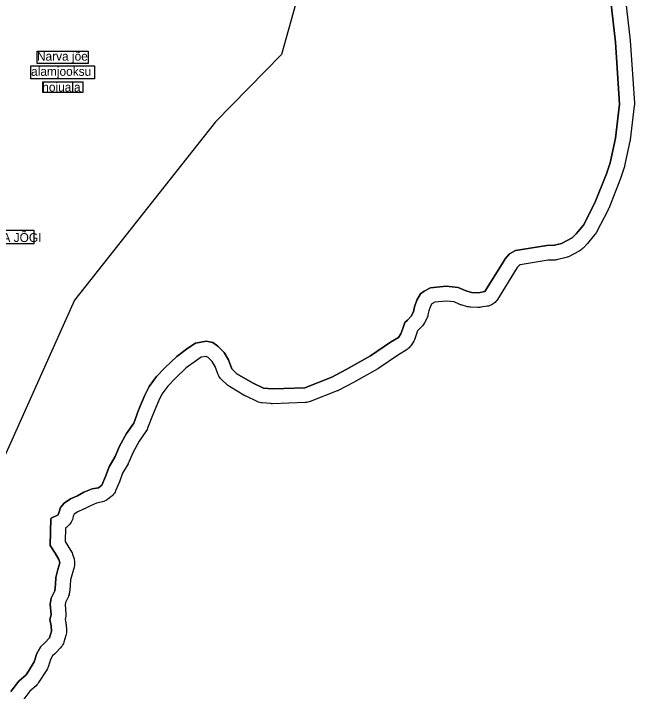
# Model space of a CAD drawing. Extents: x 728832 to 739469, y 6586263 to 6599699.
# Drawn here: x 738858.8 to 739277.9, y 6589449.5 to 6589907.2 of the extents above; entities that cross this region are included whole.
import ezdxf

# ---------------------------------------------------------------- set-up
doc = ezdxf.new("R2010")
doc.units = 0
for name, color, linetype in [('a_kalda_veekaitsev', 7, 'Continuous'), ('a_looduskaitse_voond', 7, 'Continuous'), ('a_veekogu_piir', 7, 'Continuous'), ('dp_hoonestus', 7, 'Continuous'), ('v_dp_situatsioon_tekst', 7, 'Continuous'), ('v_dp_tekst', 7, 'Continuous')]:
    doc.layers.add(name, color=color, linetype=linetype)

msp = doc.modelspace()

# ---------------------------------------------------------------- linework, layer by layer
at = {"layer": 'a_kalda_veekaitsev'}
for points in [[(738856.95, 6589449.31), (738862.4, 6589456.36), (738867.29, 6589460.76), (738868.82, 6589463.2), (738872.73, 6589469.37), (738874.42, 6589474.97), (738877.19, 6589479.75), (738880.02, 6589482.33), (738883.16, 6589485.7), (738884.51, 6589490.09), (738884.24, 6589493.84), (738883.41, 6589498.14), (738884.11, 6589501.28), (738883.63, 6589508.41), (738884.28, 6589512.41), (738886.62, 6589517.38), (738887.04, 6589521.58), (738887.26, 6589526.44), (738888.78, 6589531.84), (738890.04, 6589536.2), (738889.34, 6589538.52), (738886.8, 6589542.87), (738883.57, 6589548.02), (738883.83, 6589557.29), (738884.08, 6589565.9), (738884.09, 6589566.4), (738889.02, 6589568.73), (738889.49, 6589570.65), (738890.56, 6589573.74), (738893.03, 6589576.63), (738897.29, 6589579.6), (738902.04, 6589581.64), (738906.35, 6589583.91), (738911.89, 6589586.27), (738916.24, 6589587.04), (738918.45, 6589588.72), (738920.91, 6589594.6), (738923.38, 6589601.11), (738927.41, 6589608.16), (738930.38, 6589615.06), (738935.13, 6589623.68), (738939.96, 6589630.68), (738943.23, 6589639.37), (738947.44, 6589649.54), (738950.34, 6589655.38), (738955.29, 6589662.03), (738961, 6589668.04), (738968.98, 6589675.65), (738976.54, 6589681.24), (738981.67, 6589684.57), (738988.87, 6589685.87), (738993.27, 6589685.02), (738996.76, 6589682.58), (739000.87, 6589678.31), (739003.91, 6589673.29), (739006.09, 6589667.31), (739009.62, 6589663.94), (739020.03, 6589657.78), (739027.55, 6589654.24), (739033.37, 6589653.76), (739041.32, 6589653.93), (739055.36, 6589654.5), (739073.67, 6589661.7), (739083.31, 6589666.81), (739099.7, 6589676.05), (739113.25, 6589685.25), (739118.65, 6589688.53), (739120.26, 6589690.87), (739121.53, 6589694.46), (739122.89, 6589698.54), (739124.73, 6589700.26), (739127.25, 6589702.82), (739128.78, 6589705.84), (739129.5, 6589709.21), (739131.11, 6589713.71), (739133.47, 6589717.91), (739135.93, 6589719.79), (739140.29, 6589722.07), (739150.87, 6589723.14), (739158.82, 6589722.2), (739163.6, 6589720.09), (739167.9, 6589718.88), (739172.56, 6589718.72), (739176.97, 6589719.42), (739188.61, 6589738.24), (739190.63, 6589741.48), (739193.61, 6589745.05), (739197.67, 6589747.15), (739218.68, 6589750.55), (739223.89, 6589750.75), (739228.69, 6589751.88), (739235.93, 6589755.68), (739238.54, 6589758.47), (739243.44, 6589764.2), (739251.22, 6589779.29), (739258.94, 6589798.95), (739261.51, 6589806.46), (739265.09, 6589823.09), (739267.9, 6589846.01), (739265.09, 6589887.82), (739260.98, 6589923.4)], [(739270.92, 6589924.55), (739275.02, 6589888.97), (739277.88, 6589846.68), (739277.9, 6589846.05), (739277.88, 6589845.42), (739277.83, 6589844.79), (739275.02, 6589821.87), (739274.97, 6589821.57), (739274.92, 6589821.28), (739274.87, 6589820.98), (739271.28, 6589804.35), (739271.19, 6589803.98), (739271.09, 6589803.6), (739270.97, 6589803.23), (739268.41, 6589795.72), (739260.53, 6589775.64), (739260.4, 6589775.32), (739260.26, 6589775.01), (739260.11, 6589774.71), (739252.33, 6589759.62), (739251.95, 6589758.95), (739251.52, 6589758.31), (739251.04, 6589757.7), (739246.13, 6589751.97), (739243.24, 6589748.85), (739242.64, 6589748.26), (739241.99, 6589747.73), (739241.3, 6589747.24), (739240.58, 6589746.82), (739233.33, 6589743.02), (739232.57, 6589742.66), (739231.79, 6589742.37), (739230.98, 6589742.14), (739226.18, 6589741.01), (739225.54, 6589740.89), (739224.9, 6589740.8), (739224.26, 6589740.75), (739219.67, 6589740.58), (739200.84, 6589737.54), (739200, 6589737.1), (739198.76, 6589735.62), (739185.47, 6589714.15), (739184.99, 6589713.44), (739184.45, 6589712.78), (739183.85, 6589712.16), (739183.2, 6589711.59), (739182.5, 6589711.09), (739181.77, 6589710.64), (739181, 6589710.26), (739180.2, 6589709.95), (739179.37, 6589709.71), (739178.53, 6589709.54), (739174.12, 6589708.84), (739173.49, 6589708.77), (739172.86, 6589708.73), (739172.23, 6589708.73), (739167.57, 6589708.88), (739166.77, 6589708.94), (739165.97, 6589709.06), (739165.19, 6589709.25), (739160.89, 6589710.46), (739160.44, 6589710.6), (739159.99, 6589710.76), (739159.55, 6589710.94), (739156.15, 6589712.44), (739150.78, 6589713.08), (739143.22, 6589712.32), (739141.17, 6589711.21), (739140.24, 6589709.56), (739139.14, 6589706.47), (739138.55, 6589703.74), (739138.34, 6589702.92), (739138.06, 6589702.11), (739137.71, 6589701.34), (739136.18, 6589698.32), (739135.78, 6589697.6), (739135.33, 6589696.92), (739134.82, 6589696.28), (739134.26, 6589695.68), (739131.58, 6589693.06), (739129.71, 6589687.62), (739129.38, 6589686.78), (739128.98, 6589685.97), (739128.5, 6589685.2), (739126.89, 6589682.86), (739126.38, 6589682.19), (739125.82, 6589681.56), (739125.21, 6589680.98), (739124.55, 6589680.45), (739123.84, 6589679.98), (739118.66, 6589676.83), (739105.31, 6589667.78), (739105.08, 6589667.62), (739104.85, 6589667.48), (739104.61, 6589667.34), (739088.22, 6589658.1), (739078.35, 6589652.86), (739078.02, 6589652.69), (739077.68, 6589652.54), (739077.33, 6589652.39), (739059.02, 6589645.19), (739058.22, 6589644.91), (739057.39, 6589644.7), (739056.55, 6589644.57), (739055.7, 6589644.5), (739033.7, 6589643.76), (739033.32, 6589643.76), (739032.93, 6589643.77), (739032.54, 6589643.79), (739026.73, 6589644.27), (739025.84, 6589644.38), (739024.97, 6589644.58), (739024.12, 6589644.85), (739023.29, 6589645.19), (739015.77, 6589648.74), (739015.49, 6589648.87), (739015.21, 6589649.02), (739014.94, 6589649.17), (739004.53, 6589655.33), (739003.89, 6589655.75), (739003.28, 6589656.21), (739002.71, 6589656.71), (738999.18, 6589660.08), (738998.55, 6589660.74), (738997.98, 6589661.46), (738997.48, 6589662.23), (738997.05, 6589663.04), (738996.69, 6589663.88), (738994.85, 6589668.94), (738992.89, 6589672.18), (738990.23, 6589674.94), (738988.81, 6589675.7), (738985.42, 6589675.09), (738982.24, 6589673.02), (738975.43, 6589667.98), (738968.08, 6589660.98), (738962.95, 6589655.58), (738958.89, 6589650.12), (738956.54, 6589645.4), (738952.53, 6589635.7), (738949.32, 6589627.16), (738949, 6589626.41), (738948.62, 6589625.69), (738948.19, 6589625), (738943.65, 6589618.41), (738939.37, 6589610.66), (738936.59, 6589604.21), (738936.44, 6589603.87), (738936.27, 6589603.53), (738936.09, 6589603.2), (738932.45, 6589596.84), (738930.27, 6589591.06), (738927.67, 6589584.85), (738927.3, 6589584.06), (738926.86, 6589583.31), (738926.36, 6589582.6), (738925.79, 6589581.94), (738925.18, 6589581.33), (738924.51, 6589580.77), (738922.31, 6589579.09), (738921.52, 6589578.55), (738920.69, 6589578.09), (738919.82, 6589577.7), (738918.92, 6589577.41), (738917.99, 6589577.2), (738914.76, 6589576.62), (738910.64, 6589574.87), (738906.69, 6589572.79), (738906.46, 6589572.67), (738906.22, 6589572.56), (738905.98, 6589572.45), (738902.17, 6589570.82), (738899.8, 6589569.16), (738899.39, 6589568.67), (738899.09, 6589567.83), (738898.74, 6589566.38), (738898.49, 6589565.5), (738898.15, 6589564.65), (738897.74, 6589563.83), (738897.26, 6589563.06), (738896.71, 6589562.33), (738896.09, 6589561.66), (738895.42, 6589561.04), (738894.69, 6589560.49), (738893.91, 6589560.01), (738893.65, 6589550.69), (738897.89, 6589543.71), (738898.3, 6589542.97), (738898.64, 6589542.19), (738898.92, 6589541.39), (738899.62, 6589539.06), (738899.82, 6589538.28), (738899.95, 6589537.48), (738900.03, 6589536.67), (738900.03, 6589535.86), (738899.97, 6589535.05), (738899.84, 6589534.24), (738899.65, 6589533.45), (738897.19, 6589524.83), (738897.03, 6589521.14), (738897.02, 6589520.95), (738897.01, 6589520.76), (738896.99, 6589520.57), (738896.57, 6589516.37), (738896.44, 6589515.53), (738896.25, 6589514.71), (738895.99, 6589513.9), (738895.66, 6589513.12), (738893.93, 6589509.43), (738893.68, 6589507.94), (738894.08, 6589501.94), (738894.1, 6589500.99), (738894.03, 6589500.04), (738893.87, 6589499.1), (738893.62, 6589498), (738894.06, 6589495.75), (738894.13, 6589495.35), (738894.18, 6589494.95), (738894.22, 6589494.55), (738894.48, 6589490.8), (738894.51, 6589489.88), (738894.44, 6589488.96), (738894.3, 6589488.05), (738894.07, 6589487.16), (738892.72, 6589482.77), (738892.42, 6589481.91), (738892.04, 6589481.09), (738891.58, 6589480.31), (738891.06, 6589479.57), (738890.48, 6589478.88), (738887.34, 6589475.52), (738887.15, 6589475.32), (738886.95, 6589475.12), (738886.75, 6589474.94), (738885.07, 6589473.4), (738883.66, 6589470.96), (738882.3, 6589466.47), (738882, 6589465.63), (738881.63, 6589464.82), (738881.18, 6589464.04), (738875.75, 6589455.43), (738875.23, 6589454.67), (738874.63, 6589453.97), (738873.98, 6589453.33), (738869.76, 6589449.53), (738865.72, 6589444.3)]]:
    msp.add_lwpolyline(points, dxfattribs=at)
at = {"layer": 'a_looduskaitse_voond'}
for points in [[(738874.68, 6589881.78), (738909.22, 6589881.78), (738909.22, 6589873.48), (738874.68, 6589873.48)], [(738870.45, 6589871.79), (738913.35, 6589871.79), (738913.35, 6589863.18), (738870.45, 6589863.18)], [(738878.53, 6589861.13), (738905.68, 6589861.13), (738905.68, 6589853.91), (738878.53, 6589853.91)], [(738829.24, 6589761.03), (738872.61, 6589761.03), (738872.61, 6589751.77), (738829.24, 6589751.77)]]:
    msp.add_lwpolyline(points, close=True, dxfattribs=at)
at = {"layer": 'a_veekogu_piir'}
msp.add_lwpolyline([(739260.98, 6589923.4), (739265.09, 6589887.82), (739267.9, 6589846.01), (739265.09, 6589823.09), (739261.51, 6589806.46), (739258.94, 6589798.95), (739251.22, 6589779.29), (739243.44, 6589764.2), (739238.54, 6589758.47), (739235.93, 6589755.68), (739228.69, 6589751.88), (739223.89, 6589750.75), (739218.68, 6589750.55), (739197.67, 6589747.15), (739193.61, 6589745.05), (739190.63, 6589741.48), (739188.61, 6589738.24), (739176.97, 6589719.42), (739172.56, 6589718.72), (739167.9, 6589718.88), (739163.6, 6589720.09), (739158.82, 6589722.2), (739150.87, 6589723.14), (739140.29, 6589722.07), (739135.93, 6589719.79), (739133.47, 6589717.91), (739131.11, 6589713.71), (739129.5, 6589709.21), (739128.78, 6589705.84), (739127.25, 6589702.82), (739124.73, 6589700.26), (739122.89, 6589698.54), (739121.53, 6589694.46), (739120.26, 6589690.87), (739118.65, 6589688.53), (739113.25, 6589685.25), (739099.7, 6589676.05), (739083.31, 6589666.81), (739073.67, 6589661.7), (739055.36, 6589654.5), (739041.32, 6589653.93), (739033.37, 6589653.76), (739027.55, 6589654.24), (739020.03, 6589657.78), (739009.62, 6589663.94), (739006.09, 6589667.31), (739003.91, 6589673.29), (739000.87, 6589678.31), (738996.76, 6589682.58), (738993.27, 6589685.02), (738988.87, 6589685.87), (738981.67, 6589684.57), (738976.54, 6589681.24), (738968.98, 6589675.65), (738961, 6589668.04), (738955.29, 6589662.03), (738950.34, 6589655.38), (738947.44, 6589649.54), (738943.23, 6589639.37), (738939.96, 6589630.68), (738935.13, 6589623.68), (738930.38, 6589615.06), (738927.41, 6589608.16), (738923.38, 6589601.11), (738920.91, 6589594.6), (738918.45, 6589588.72), (738916.24, 6589587.04), (738911.89, 6589586.27), (738906.35, 6589583.91), (738902.04, 6589581.64), (738897.29, 6589579.6), (738893.03, 6589576.63), (738890.56, 6589573.74), (738889.49, 6589570.65), (738889.02, 6589568.73), (738884.09, 6589566.4), (738884.08, 6589565.9), (738883.83, 6589557.29), (738883.57, 6589548.02), (738886.8, 6589542.87), (738889.34, 6589538.52), (738890.04, 6589536.2), (738888.78, 6589531.84), (738887.26, 6589526.44), (738887.04, 6589521.58), (738886.62, 6589517.38), (738884.28, 6589512.41), (738883.63, 6589508.41), (738884.11, 6589501.28), (738883.41, 6589498.14), (738884.24, 6589493.84), (738884.51, 6589490.09), (738883.16, 6589485.7), (738880.02, 6589482.33), (738877.19, 6589479.75), (738874.42, 6589474.97), (738872.73, 6589469.37), (738868.82, 6589463.2), (738867.29, 6589460.76), (738862.4, 6589456.36), (738856.95, 6589449.31)], dxfattribs=at)
at = {"layer": 'dp_hoonestus'}
msp.add_lwpolyline([(738544.55, 6591130.54), (738777.58, 6590706.02), (738824.58, 6590644.12), (738867.62, 6590606.55), (738942.09, 6590474.98), (739017.23, 6590295.07), (739034.11, 6590232.51), (739063.74, 6589965.72), (739039.57, 6589879.66), (738995.22, 6589833.98), (738899.89, 6589713.66), (738848.75, 6589599.46), (738792.31, 6589420.72)], dxfattribs=at)
msp.add_lwpolyline([(738544.55, 6591130.54), (738777.58, 6590706.02), (738824.58, 6590644.12), (738867.62, 6590606.55), (738942.09, 6590474.98), (739017.23, 6590295.07), (739034.11, 6590232.51), (739063.74, 6589965.72), (739039.57, 6589879.66), (738995.22, 6589833.98), (738899.89, 6589713.66), (738848.75, 6589599.46), (738792.31, 6589420.72)], dxfattribs=at)

# ---------------------------------------------------------------- texts
at = {"layer": 'v_dp_situatsioon_tekst'}
msp.add_text('NARVA JÕGI', height=6, dxfattribs=at).set_placement((738829.02, 6589752.94))
at = {"layer": 'v_dp_tekst'}
for s, p in [('Narva jõe', (738874.6, 6589875.4)), ('alamjooksu', (738870.66, 6589865.15)), ('hoiuala', (738878.19, 6589854.5))]:
    msp.add_text(s, height=6, dxfattribs=at).set_placement(p)

doc.saveas('drawing.dxf')
